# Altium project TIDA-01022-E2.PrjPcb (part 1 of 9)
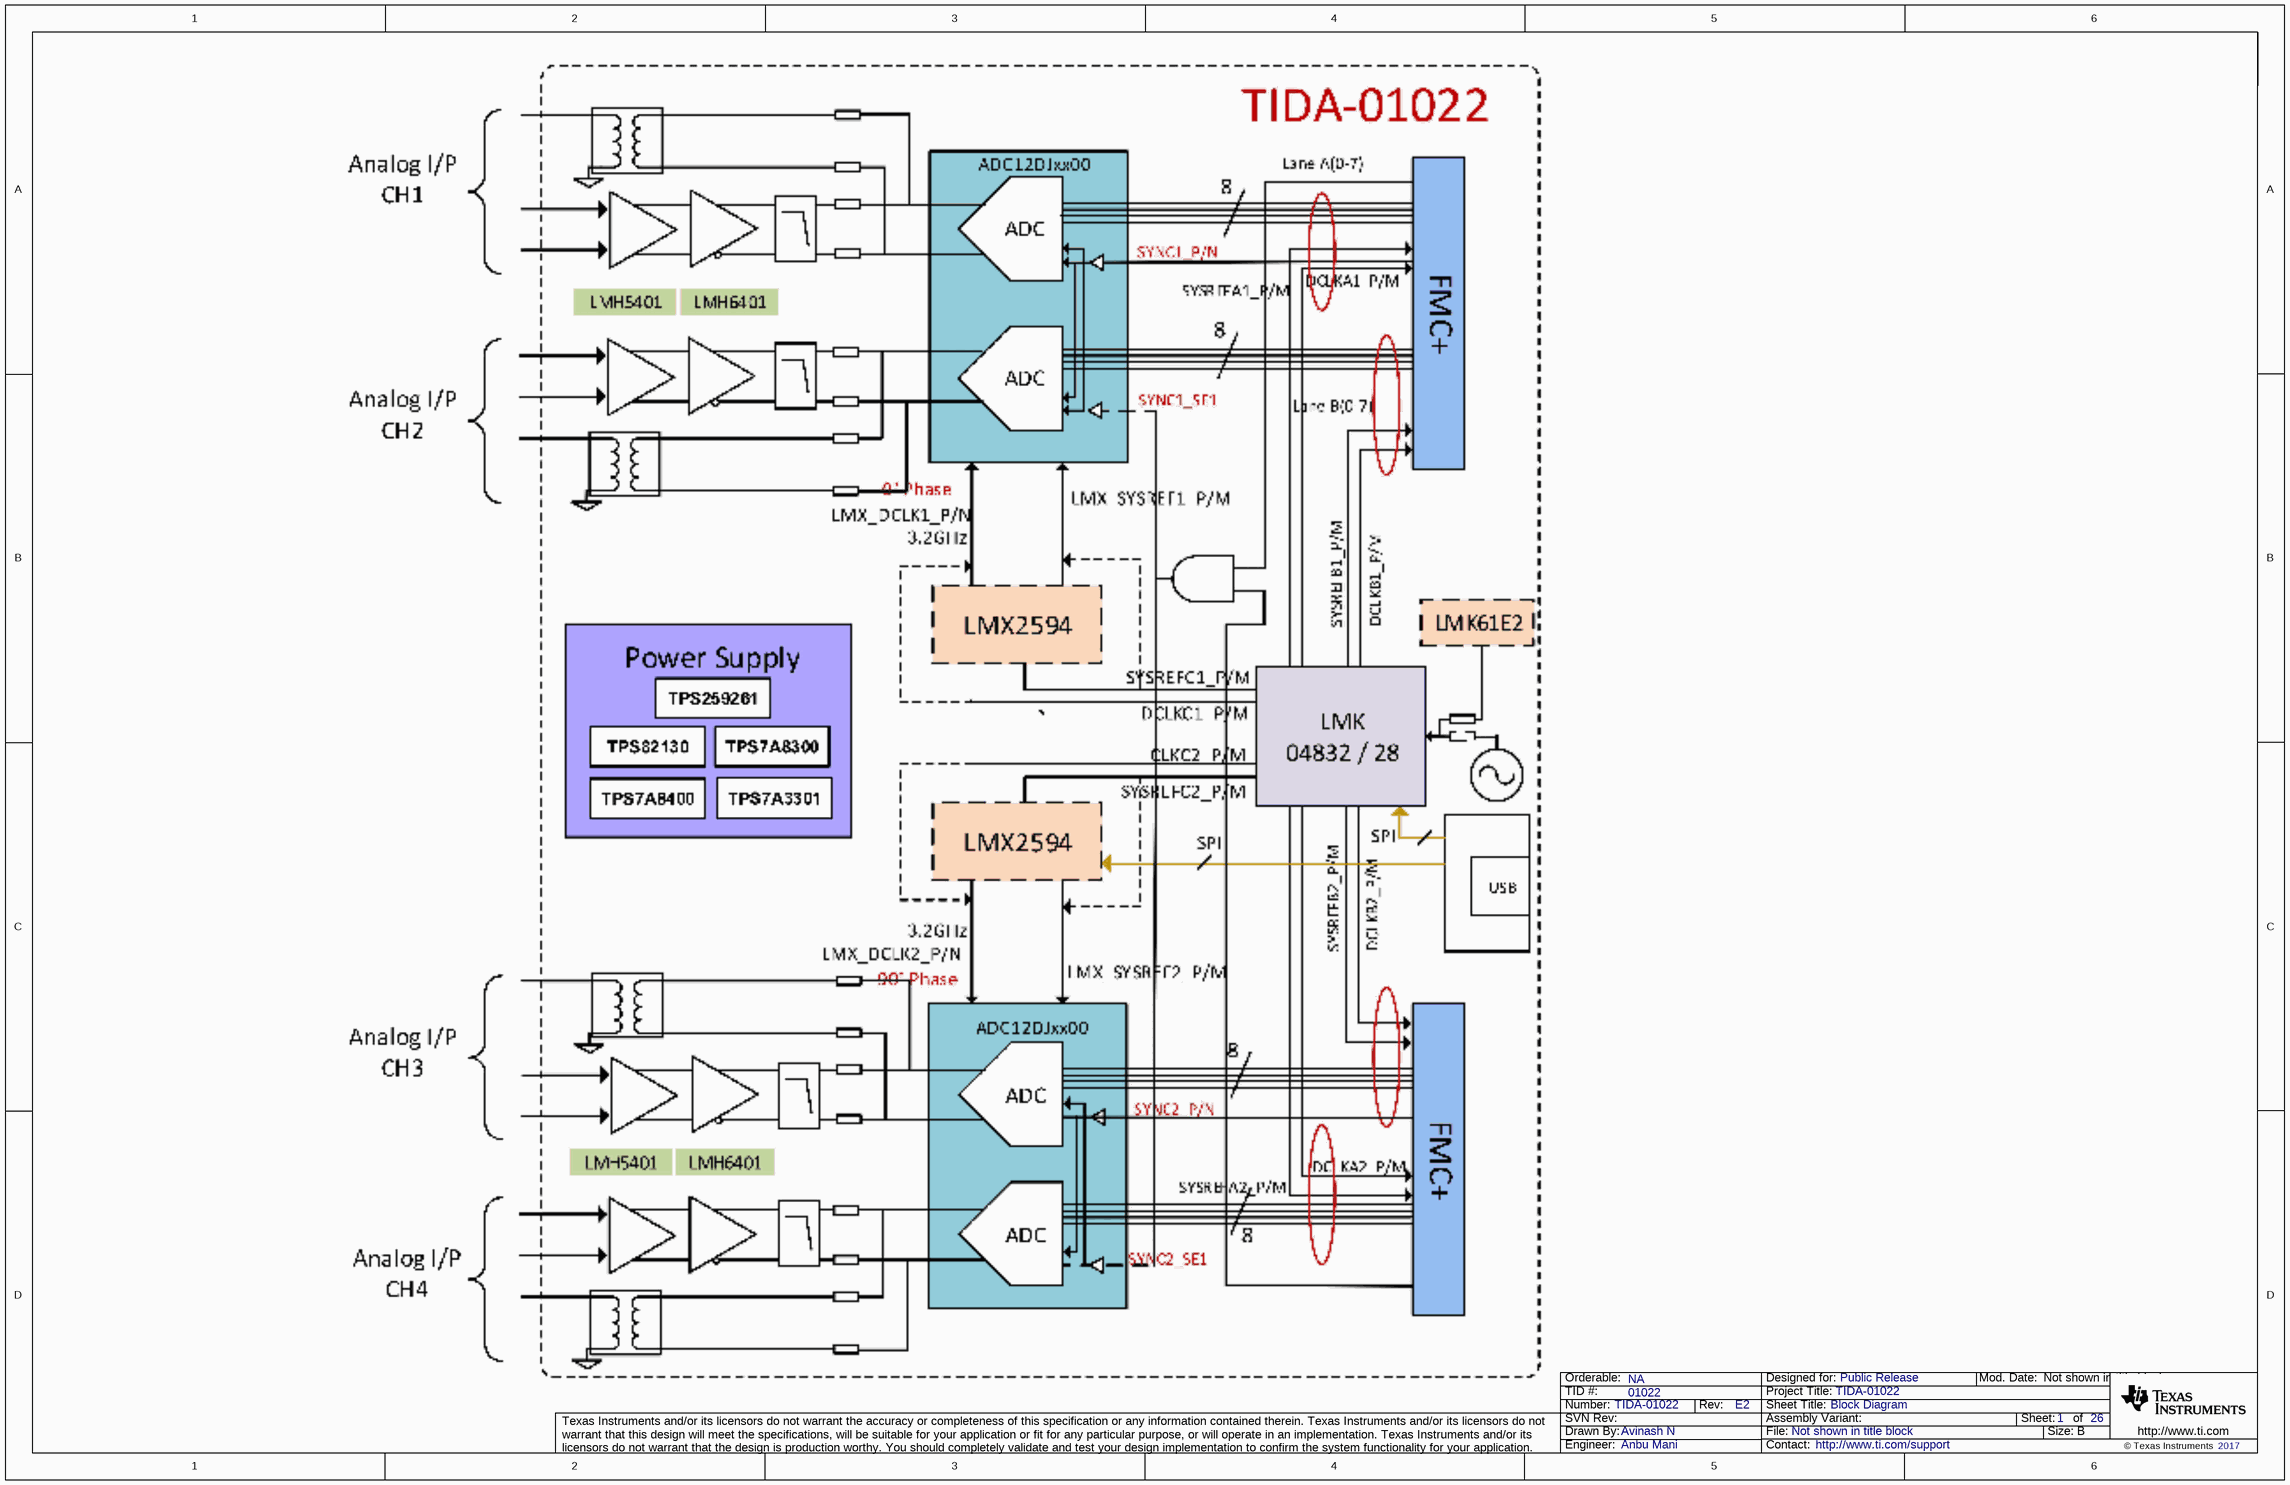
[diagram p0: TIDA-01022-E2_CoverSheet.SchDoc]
CopyrightYear: 2017; EVM_orderable: NA; PCB_Layout: Avinash N; PCB_Rev: E2; PRJ_Customer: Public Release; PRJ_Engineer: Anbu Mani; PRJ_Number: TIDA-01022; PRJ_Title: TIDA-01022; SCH_Rev: E2; TechSupport: http://www.ti.com/support; TID: 01022
26 sheets, 1781 parts. Net scope: flat (ports and power ports of the same name join across sheets).
Board file: TIDA-01022-E2.PcbDoc
Sheets:
  TIDA-01022-E2_CoverSheet.SchDoc
  TIDA-01022-E2_ADC ANALOG INP CH1.SchDoc
  TIDA-01022-E2_ADC ANALOG INP CH2.SchDoc
  TIDA-01022-E2_ADC ANALOG INP CH3.SchDoc
  TIDA-01022-E2_ADC ANALOG INP CH4.SchDoc
  TIDA-01022-E2_ADC12DJxx00_1.SchDoc
  TIDA-01022-E2_ADC12DJxx00_1PWR.SchDoc
  TIDA-01022-E2_ADC12DJxx00_2.SchDoc
  TIDA-01022-E2_ADC12DJxx00_2PWR.SchDoc
  TIDA-01022-E2_LMK00304_Buffer.SchDoc
  TIDA-01022-E2_LMK0482x.SchDoc
  TIDA-01022-E2_LMK0482x _PWR.SchDoc
  TIDA-01022-E2_LMX2594R_1.SchDoc
  TIDA-01022-E2_LMX2594R_2.SchDoc
  TIDA-01022-E2_Programming for ADC_LMK _LMX.SchDoc
  TIDA-01022-E2_USB.SchDoc
  TIDA-01022-E2_FMC+CONN1_1.SchDoc
  TIDA-01022-E2_FMC+CONN1_2.SchDoc
  TIDA-01022-E2_FMC+CONN2_1.SchDoc
  TIDA-01022-E2_FMC+CONN2_2.SchDoc
  TIDA-01022-E2_Power1.SchDoc
  TIDA-01022-E2_Power2.SchDoc
  TIDA-01022-E2_Power3.SchDoc
  TIDA-01022-E2_Power4.SchDoc
  TIDA-01022-E2_Power5.SchDoc
  TIDA-01022-E2_Hardware.SchDoc

## Sheet TIDA-01022-E2_CoverSheet.SchDoc: Block Diagram
size 431 x 279 mm; Date: Not shown in title block; ApprovedBy: Not shown in title block; CheckedBy: Not shown in title block; Author: Not shown in title block; CompanyName: Not shown in title block; DrawnBy: Avinash N; Engineer: Not shown in title block; Organization: Not shown in title block; Address1: Not shown in title block; Address2: Not shown in title block; Address3: Not shown in title block; Address4: Not shown in title block; DocumentNumber: 1; Revision: Use project parameter SCH_Rev; SheetNumber: 1; SheetTotal: 26; PageSetup: Record=PageOptions¦CenterHorizontal=True¦CenterVertical=True¦PrintScale=1.00¦XCorrection=1.00¦YCorrection=1.00¦PrintKind=0¦BorderSize=5000000¦LeftOffset=0¦BottomOffset=0¦Orientation=2¦PaperLength=1000¦PaperWidth=1000¦Scale=100¦PaperSource=15¦PrintQuality=600¦MediaType=1¦DitherType=10¦PaperKind=Letter¦PrintScaleMode=1

## Sheet TIDA-01022-E2_ADC ANALOG INP CH1.SchDoc: ADC ANALOG INP CH1
size 431 x 279 mm; Date: Not shown in title block; ApprovedBy: Not shown in title block; CheckedBy: Not shown in title block; Author: Not shown in title block; CompanyName: Not shown in title block; DrawnBy: Avinash N; Engineer: Not shown in title block; Organization: Not shown in title block; Address1: Not shown in title block; Address2: Not shown in title block; Address3: Not shown in title block; Address4: Not shown in title block; DocumentNumber: 1; Revision: Use project parameter SCH_Rev; SheetNumber: 2; SheetTotal: 26; PageSetup: Record=PageOptions¦CenterHorizontal=True¦CenterVertical=True¦PrintScale=1.00¦XCorrection=1.00¦YCorrection=1.00¦PrintKind=0¦BorderSize=5000000¦LeftOffset=0¦BottomOffset=0¦Orientation=2¦PaperLength=1000¦PaperWidth=1000¦Scale=100¦PaperSource=15¦PrintQuality=600¦MediaType=1¦DitherType=10¦PaperKind=Letter¦PrintScaleMode=1
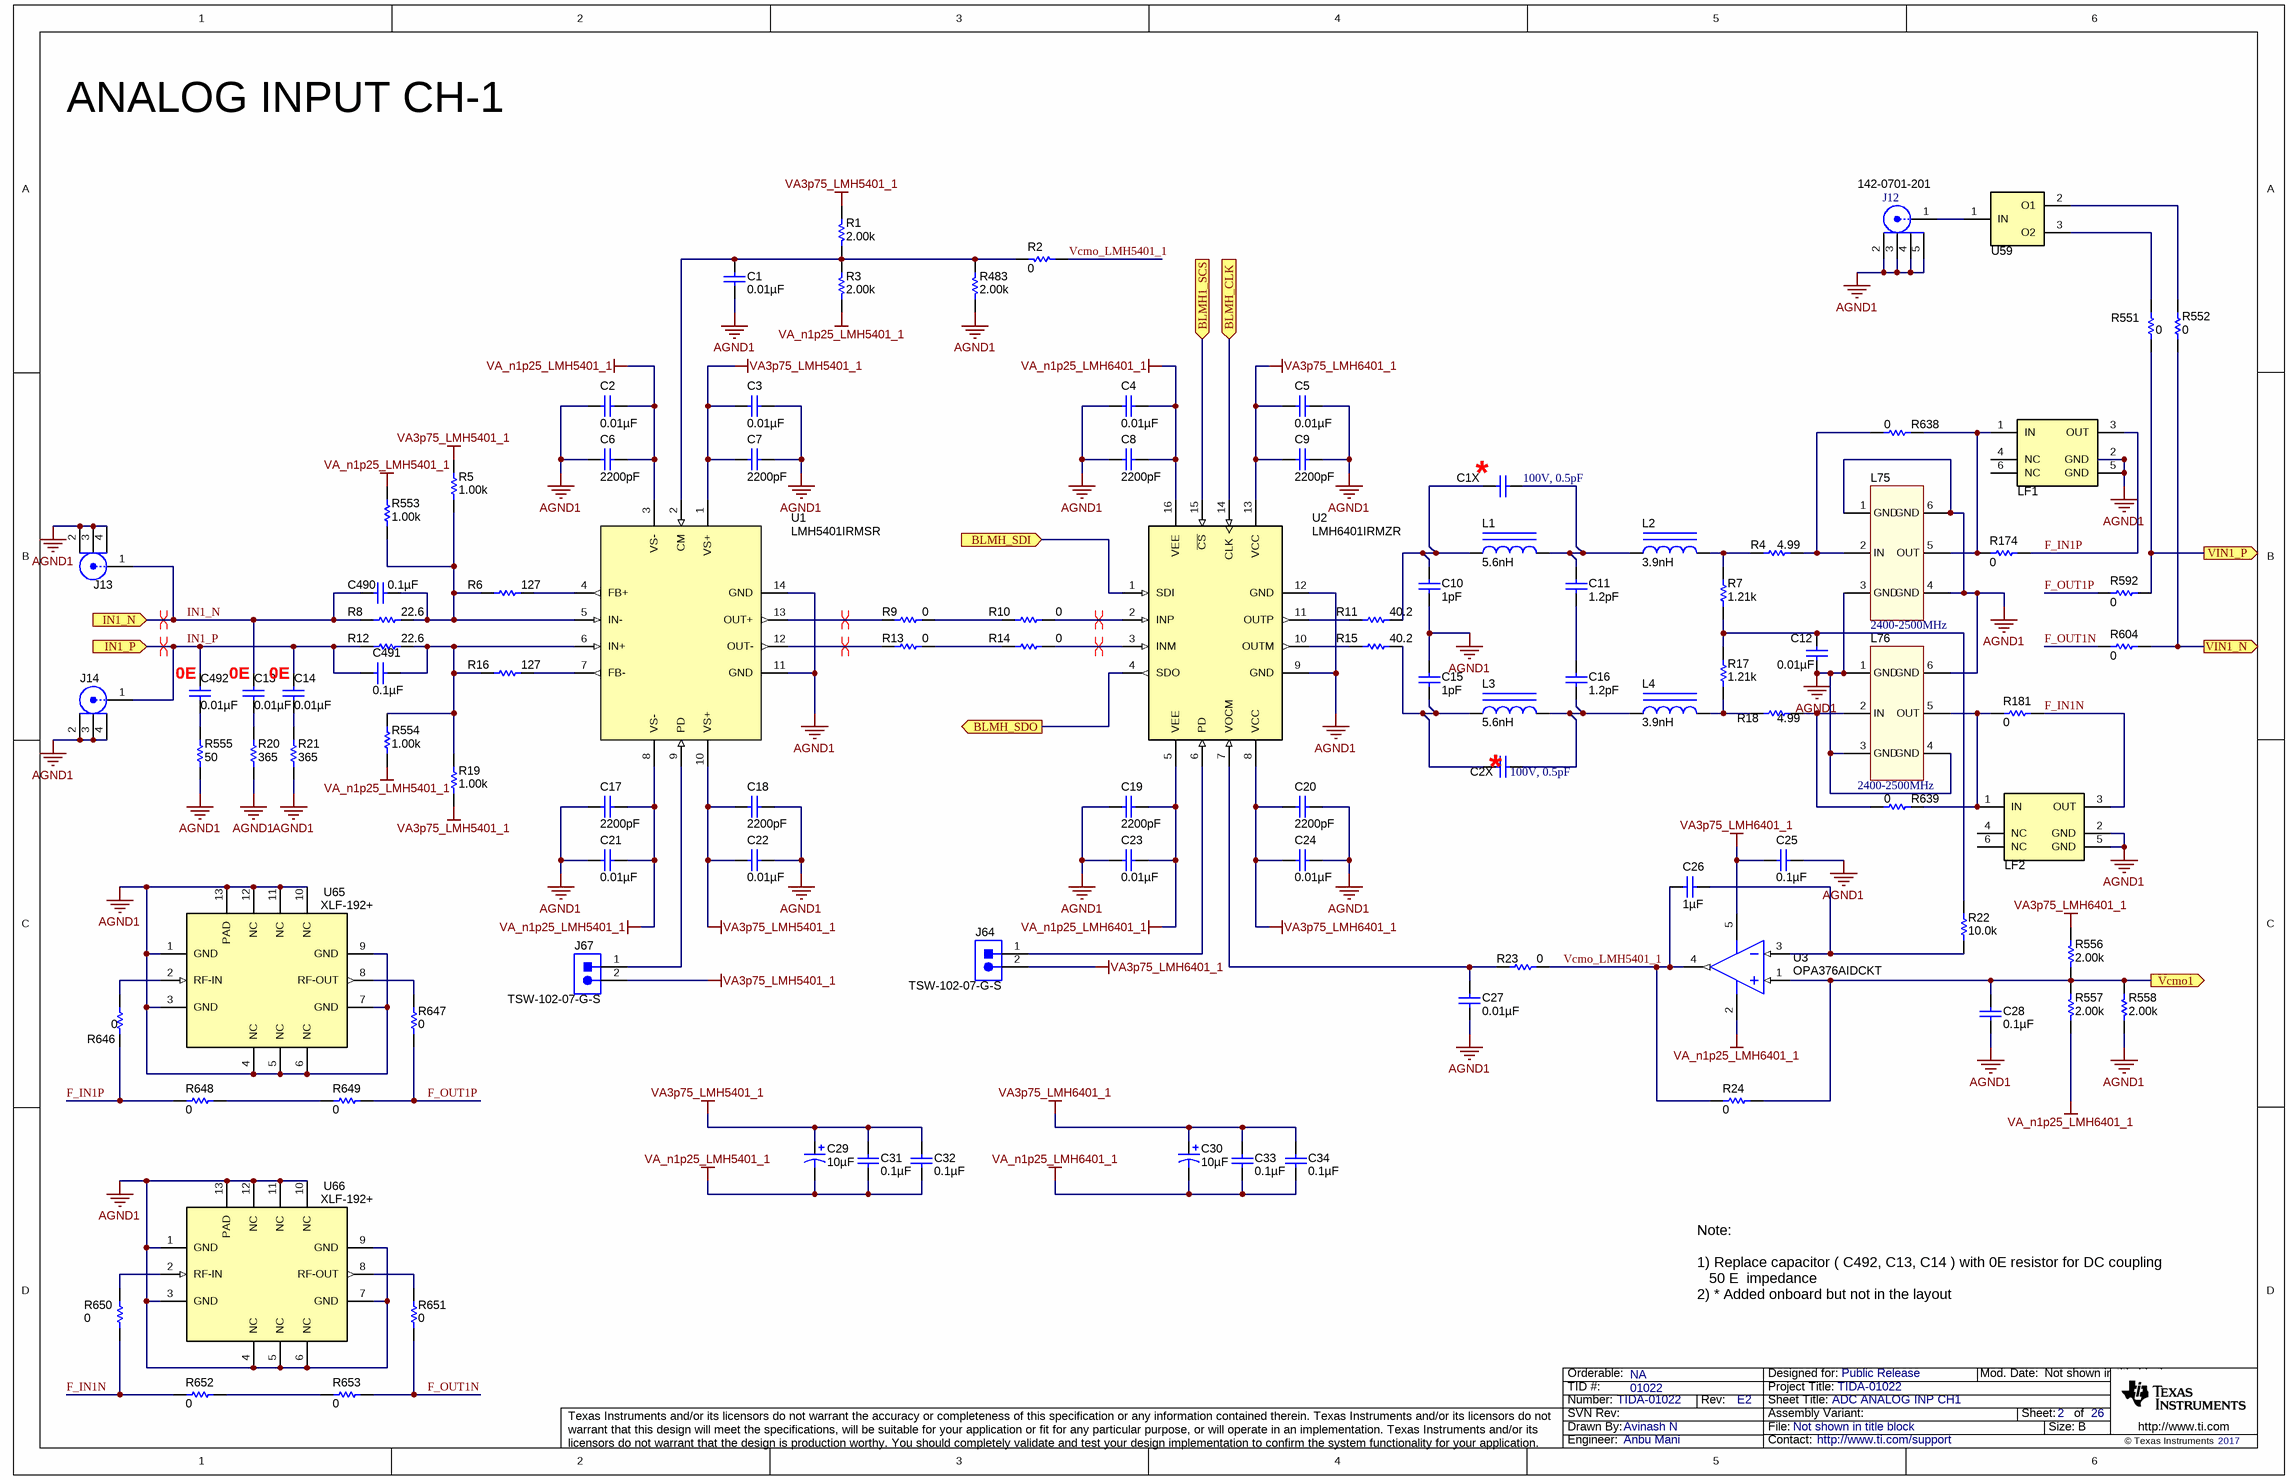
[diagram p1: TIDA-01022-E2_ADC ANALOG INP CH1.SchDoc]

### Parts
C1  ValueDisplayed: 0.01µF  [0402]  (hidden comment: GRM155R71E103KA01D)
C1X  100V, 0.5pF  [0603_1.6x0.8x0.8mm_Reflow Soldering]
C2  ValueDisplayed: 0.01µF  [0306]  (hidden comment: LLL185R71E103MA01L)
C2X  100V, 0.5pF  [0603_1.6x0.8x0.8mm_Reflow Soldering]
C3  ValueDisplayed: 0.01µF  [0306]  (hidden comment: LLL185R71E103MA01L)
C4  ValueDisplayed: 0.01µF  [0306]  (hidden comment: LLL185R71E103MA01L)
C5  ValueDisplayed: 0.01µF  [0306]  (hidden comment: LLL185R71E103MA01L)
C6  ValueDisplayed: 2200pF  [0306]  (hidden comment: LLL185R71H222MA01L)
C7  ValueDisplayed: 2200pF  [0306]  (hidden comment: LLL185R71H222MA01L)
C8  ValueDisplayed: 2200pF  [0306]  (hidden comment: LLL185R71H222MA01L)
C9  ValueDisplayed: 2200pF  [0306]  (hidden comment: LLL185R71H222MA01L)
C10  ValueDisplayed: 1pF  [0402]  (hidden comment: GRM1555C1H1R0CA01D)
C11  ValueDisplayed: 1.2pF  [0402]  (hidden comment: GRM1555C1H1R2BA01D)
C12  ValueDisplayed: 0.01µF  [0402]  (hidden comment: GRM155R71E103KA01D)
C13  ValueDisplayed: 0.01µF  [0402]  (hidden comment: GRM155R71E103KA01D)
C14  ValueDisplayed: 0.01µF  [0402]  (hidden comment: GRM155R71E103KA01D)
C15  ValueDisplayed: 1pF  [0402]  (hidden comment: GRM1555C1H1R0CA01D)
C16  ValueDisplayed: 1.2pF  [0402]  (hidden comment: GRM1555C1H1R2BA01D)
C17  ValueDisplayed: 2200pF  [0306]  (hidden comment: LLL185R71H222MA01L)
C18  ValueDisplayed: 2200pF  [0306]  (hidden comment: LLL185R71H222MA01L)
C19  ValueDisplayed: 2200pF  [0306]  (hidden comment: LLL185R71H222MA01L)
C20  ValueDisplayed: 2200pF  [0306]  (hidden comment: LLL185R71H222MA01L)
C21  ValueDisplayed: 0.01µF  [0306]  (hidden comment: LLL185R71E103MA01L)
C22  ValueDisplayed: 0.01µF  [0306]  (hidden comment: LLL185R71E103MA01L)
C23  ValueDisplayed: 0.01µF  [0306]  (hidden comment: LLL185R71E103MA01L)
C24  ValueDisplayed: 0.01µF  [0306]  (hidden comment: LLL185R71E103MA01L)
C25  ValueDisplayed: 0.1µF  [0402]  (hidden comment: C1005X5R1A104K050BA)
C26  ValueDisplayed: 1µF  [0603]  (hidden comment: C1608X5R1A105K080AC)
C27  ValueDisplayed: 0.01µF  [0402]  (hidden comment: GRM155R71E103KA01D)
C28  ValueDisplayed: 0.1µF  [0402]  (hidden comment: C1005X5R1A104K050BA)
C29  ValueDisplayed: 10µF  [3216-18]  (hidden comment: TPSA106K010R0900)
C30  ValueDisplayed: 10µF  [3216-18]  (hidden comment: TPSA106K010R0900)
C31  ValueDisplayed: 0.1µF  [0402]  (hidden comment: C1005X5R1A104K050BA)
C32  ValueDisplayed: 0.1µF  [0402]  (hidden comment: C1005X5R1A104K050BA)
C33  ValueDisplayed: 0.1µF  [0402]  (hidden comment: C1005X5R1A104K050BA)
C34  ValueDisplayed: 0.1µF  [0402]  (hidden comment: C1005X5R1A104K050BA)
C490  ValueDisplayed: 0.1µF  [0402]  (hidden comment: GRM155R71C104JA88D)
C491  ValueDisplayed: 0.1µF  [0402]  (hidden comment: GRM155R71C104JA88D)
C492  ValueDisplayed: 0.01µF  [0402]  (hidden comment: GRM155R71E103KA01D)
J12  142-0701-201  [Johnson_142-0701-20x]
J13  142-0771-831  [Johnson_142-0771-831]  (value not drawn)
J14  142-0771-831  [Johnson_142-0771-831]  (value not drawn)
J64  TSW-102-07-G-S  [TSW-102-07-G-S]
J67  TSW-102-07-G-S  [TSW-102-07-G-S]
L1  ValueDisplayed: 5.6nH  [LQW18A]  (hidden comment: LQW18AN5N6D10D)
L2  ValueDisplayed: 3.9nH  [0603HC]  (hidden comment: 0603HC-3N9XJLU)
L3  ValueDisplayed: 5.6nH  [LQW18A]  (hidden comment: LQW18AN5N6D10D)
L4  ValueDisplayed: 3.9nH  [0603HC]  (hidden comment: 0603HC-3N9XJLU)
L75  value 2400-2500MHz  [WE-LPF_0603]  (hidden comment: WE-LPF, 748112024)
L76  value 2400-2500MHz  [WE-LPF_0603]  (hidden comment: WE-LPF, 748112024)
LF1  LFL182G45TC3B746  [FIL_LFL18_TC1]  (value not drawn)
LF2  LFL182G45TC3B746  [FIL_LFL18_TC1]  (value not drawn)
R1  ValueDisplayed: 2.00k  [0402]  (hidden comment: CRCW04022K00FKED)
R2  ValueDisplayed: 0  [0402]  (hidden comment: CRCW04020000Z0ED)
R3  ValueDisplayed: 2.00k  [0402]  (hidden comment: CRCW04022K00FKED)
R4  ValueDisplayed: 4.99  [0402]  (hidden comment: CRCW04024R99FKED)
R5  ValueDisplayed: 1.00k  [0402]  (hidden comment: ERJ-2RKF1001X)
R6  ValueDisplayed: 127  [0402]  (hidden comment: CRCW0402127RFKED)
R7  ValueDisplayed: 1.21k  [0402]  (hidden comment: CRCW04021K21FKED)
R8  ValueDisplayed: 22.6  [0402]  (hidden comment: CRCW040222R6FKED)
R9  ValueDisplayed: 0  [0402]  (hidden comment: CRCW04020000Z0ED)
R10  ValueDisplayed: 0  [0402]  (hidden comment: CRCW04020000Z0ED)
R11  ValueDisplayed: 40.2  [0402]  (hidden comment: CRCW040240R2FKED)
R12  ValueDisplayed: 22.6  [0402]  (hidden comment: CRCW040222R6FKED)
R13  ValueDisplayed: 0  [0402]  (hidden comment: CRCW04020000Z0ED)
R14  ValueDisplayed: 0  [0402]  (hidden comment: CRCW04020000Z0ED)
R15  ValueDisplayed: 40.2  [0402]  (hidden comment: CRCW040240R2FKED)
R16  ValueDisplayed: 127  [0402]  (hidden comment: CRCW0402127RFKED)
R17  ValueDisplayed: 1.21k  [0402]  (hidden comment: CRCW04021K21FKED)
R18  ValueDisplayed: 4.99  [0402]  (hidden comment: CRCW04024R99FKED)
R19  ValueDisplayed: 1.00k  [0402]  (hidden comment: ERJ-2RKF1001X)
R20  ValueDisplayed: 365  [0402]  (hidden comment: CRCW0402365RFKED)
R21  ValueDisplayed: 365  [0402]  (hidden comment: CRCW0402365RFKED)
R22  ValueDisplayed: 10.0k  [0402]  (hidden comment: CRCW040210K0FKED)
R23  ValueDisplayed: 0  [0402]  (hidden comment: CRCW04020000Z0ED)
R24  ValueDisplayed: 0  [0402]  (hidden comment: CRCW04020000Z0ED)
R174  ValueDisplayed: 0  [0402_FILTER]  (hidden comment: CRCW04020000Z0ED)
R181  ValueDisplayed: 0  [0402_FILTER]  (hidden comment: CRCW04020000Z0ED)
R483  ValueDisplayed: 2.00k  [0402]  (hidden comment: CRCW04022K00FKED)
R551  ValueDisplayed: 0  [0201_adc]  (hidden comment: CRCW02010000Z0ED)
R552  ValueDisplayed: 0  [0201_adc]  (hidden comment: CRCW02010000Z0ED)
R553  ValueDisplayed: 1.00k  [0402]  (hidden comment: ERJ-2RKF1001X)
R554  ValueDisplayed: 1.00k  [0402]  (hidden comment: ERJ-2RKF1001X)
R555  ValueDisplayed: 50  [0402]  (hidden comment: FC0402E50R0BTBST1)
R556  ValueDisplayed: 2.00k  [0402]  (hidden comment: CRCW04022K00FKED)
R557  ValueDisplayed: 2.00k  [0402]  (hidden comment: CRCW04022K00FKED)
R558  ValueDisplayed: 2.00k  [0402]  (hidden comment: CRCW04022K00FKED)
R592  ValueDisplayed: 0  [0201_adc]  (hidden comment: CRCW02010000Z0ED)
R604  ValueDisplayed: 0  [0201_adc]  (hidden comment: CRCW02010000Z0ED)
R638  ValueDisplayed: 0  [0402_FILTER]  (hidden comment: CRCW04020000Z0ED)
R639  ValueDisplayed: 0  [0402_FILTER]  (hidden comment: CRCW04020000Z0ED)
R646  ValueDisplayed: 0  [0201_adc]  (hidden comment: CRCW02010000Z0ED)
R647  ValueDisplayed: 0  [0201_adc]  (hidden comment: CRCW02010000Z0ED)
R648  ValueDisplayed: 0  [0201_adc]  (hidden comment: CRCW02010000Z0ED)
R649  ValueDisplayed: 0  [0201_adc]  (hidden comment: CRCW02010000Z0ED)
R650  ValueDisplayed: 0  [0201_adc]  (hidden comment: CRCW02010000Z0ED)
R651  ValueDisplayed: 0  [0201_adc]  (hidden comment: CRCW02010000Z0ED)
R652  ValueDisplayed: 0  [0201_adc]  (hidden comment: CRCW02010000Z0ED)
R653  ValueDisplayed: 0  [0201_adc]  (hidden comment: CRCW02010000Z0ED)
U1  LMH5401IRMSR  [RMS0014A]
U2  LMH6401IRMZR  [RMZ0016A]
U3  OPA376AIDCKT  [DCK0005A_N]
U59  BAL-0006SMG  [Marki_BAL-0006SMG]  (value not drawn)
U65  XLF-192+  [DQ1225]
U66  XLF-192+  [DQ1225]

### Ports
BLMH1_SCS (in), BLMH_CLK (in), BLMH_SDI (in), BLMH_SDO (out), IN1_N (in), IN1_P (in), Vcmo1 (out), VIN1_N (out), VIN1_P (out)

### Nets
AGND1: C1.2 C2.1 C3.1 C4.1 C5.1 C6.2 C7.2 C8.2 C9.2 C10.2 C12.2 C15.2 C17.2 C18.2 C19.2 C20.2 C21.1 C22.1 C23.1 C24.1 C25.1 C27.2 C28.2 J12.2 J12.3 J12.4 J12.5 J13.2 J13.3 J13.4 J14.2 J14.3 J14.4 L75.1(GND) L75.3(GND) L75.4(GND) L75.6(GND) L76.1(GND) L76.3(GND) L76.4(GND) L76.6(GND) LF1.2(GND) LF1.5(GND) LF2.2(GND) LF2.5(GND) R20.1 R21.1 R483.1 R555.1 R558.1 U1.11(GND) U1.14(GND) U2.9(GND) U2.12(GND) U65.1(GND) U65.3(GND) U65.4(NC) U65.5(NC) U65.6(NC) U65.7(GND) U65.9(GND) U65.10(NC) U65.11(NC) U65.12(NC) U65.13(PAD) U66.1(GND) U66.3(GND) U66.4(NC) U66.5(NC) U66.6(NC) U66.7(GND) U66.9(GND) U66.10(NC) U66.11(NC) U66.12(NC) U66.13(PAD)  [project net AGND]
VA3p75_LMH5401_1: C3.2 C7.1 C18.1 C22.2 C29.1(+) C31.1 C32.1 J67.2 R1.2 R5.2 R19.1 U1.1(VS+) U1.10(VS+)
VA3p75_LMH6401_1: C5.2 C9.1 C20.1 C24.2 C25.2 C30.1(+) C33.1 C34.1 J64.2 R556.2 U2.8(VCC) U2.13(VCC) U3.5(V+)
VA_n1p25_LMH5401_1: C2.2 C6.1 C17.1 C21.2 C29.2(-) C31.2 C32.2 R3.1 R553.2 R554.2 U1.3(VS-) U1.8(VS-)
VA_n1p25_LMH6401_1: C4.2 C8.1 C19.1 C23.2 C30.2(-) C33.2 C34.2 R557.1 U2.5(VEE) U2.16(VEE) U3.2(V-)
BLMH1_SCS: U2.15(~{CS}) ; port BLMH1_SCS
BLMH_CLK: U2.14(CLK) ; port BLMH_CLK
BLMH_SDI: U2.1(SDI) ; port BLMH_SDI
BLMH_SDO: U2.4(SDO) ; port BLMH_SDO
F_IN1N: LF2.3(OUT) R181.2 R650.1 R652.1
F_IN1P: LF1.3(OUT) R174.2 R646.1 R648.1
F_OUT1N: R604.1 R651.1 R653.2
F_OUT1P: R592.1 R647.1 R649.2
IN1_N: C13.1 C490.2 J13.1 R8.1 ; port IN1_N
IN1_P: C14.1 C491.1 C492.1 J14.1 R12.1 ; port IN1_P
Vcmo1: C28.1 R24.1 R556.1 R557.2 R558.2 U3.1(IN+) ; port Vcmo1
Vcmo_LMH5401_1: C26.1 R2.2 R23.1 R24.2 U3.4(OUT)
VIN1_N: R552.2 R604.2 ; port VIN1_N
VIN1_P: R551.2 R592.2 ; port VIN1_P
NetC1_1: C1.1 R1.1 R2.1 R3.2 R483.2 U1.2(CM)
NetC1X_1: C1X.1 C10.1 L1.1 R11.1
NetC1X_2: C1X.2 C11.1 L1.2 L2.1
NetC2X_1: C2X.1 C15.1 L3.1 R15.1
NetC2X_2: C2X.2 C16.1 L3.2 L4.1
NetC11_2: C11.2 C16.2
NetC12_1: C12.1 R7.1 R17.1 R22.2
NetC13_2: C13.2 R20.2
NetC14_2: C14.2 R21.2
NetC26_2: C26.2 R22.1 U3.3(IN-)
NetC27_1: C27.1 R23.2 U2.7(VOCM)
NetC490_1: C490.1 R5.1 R6.1 R8.2 R553.1 U1.5(IN-)
NetC491_2: C491.2 R12.2 R16.1 R19.2 R554.1 U1.6(IN+)
NetC492_2: C492.2 R555.2
NetJ12_1: J12.1 U59.1(IN)
NetJ64_1: J64.1 U2.6(PD)
NetJ67_1: J67.1 U1.9(PD)
NetL2_2: L2.2 R4.1 R7.2
NetL4_2: L4.2 R17.2 R18.1
NetL75_2: L75.2(IN) R4.2 R638.1
NetL75_5: L75.5(OUT) LF1.1(IN) R174.1 R638.2
NetL76_2: L76.2(IN) R18.2 R639.1
NetL76_5: L76.5(OUT) LF2.1(IN) R181.1 R639.2
NetR6_2: R6.2 U1.4(FB+)
NetR9_1: R9.1 U1.13(OUT+)
NetR9_2: R9.2 R10.2
NetR10_1: R10.1 U2.2(INP)
NetR11_2: R11.2 U2.11(OUTP)
NetR13_1: R13.1 U1.12(OUT-)
NetR13_2: R13.2 R14.2
NetR14_1: R14.1 U2.3(INM)
NetR15_2: R15.2 U2.10(OUTM)
NetR16_2: R16.2 U1.7(FB-)
NetR551_1: R551.1 U59.3(O2)
NetR552_1: R552.1 U59.2(O1)
NetR646_2: R646.2 U65.2(RF-IN)
NetR647_2: R647.2 U65.8(RF-OUT)
NetR648_2: R648.2 R649.1
NetR650_2: R650.2 U66.2(RF-IN)
NetR651_2: R651.2 U66.8(RF-OUT)
NetR652_2: R652.2 R653.1

Not connected (* = marked no-connect by the designer): LF1 4(NC) 6(NC); LF2 4(NC) 6(NC)

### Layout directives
differential pair: IN1_N, IN1_P, NetR9_1, NetR10_1, NetR13_1, NetR14_1

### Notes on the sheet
- ANALOG INPUT CH-1
- (near C1X) *
- (near C492) 0E
- (near C13) 0E
- (near C14) 0E
- (near C2X) *
- Note:
  1) Replace capacitor ( C492, C13, C14 ) with 0E resistor for DC coupling
  50 E  impedance
  2) * Added onboard but not in the layout

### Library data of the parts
C1 C12-C14 C27 C492 = GRM155R71E103KA01D: CAP, CERM, 0.01 µF, 25 V, +/- 10%, X7R, 0402; Manufacturer: MuRata; Polarized: N; CompType: Capacitor; Value: 0.01uF; U/M: EA; Cap_F: 0.00000001; Tolerance_%: 10; Value1: Unknown; VDC_V: 25; Value2: 25V; TaMin_C: -55; TaMax_C: 125; SizeArea_mm2: 0.5; SizeAreaWB_mm2: 3; SizeX_mm: 1; SizeZ_mm: 0.6; AEC Category: Q200
C1X C2X = 885012006086: WCAP-CSGP Ceramic Capacitors, 0603, NP0, 100V, 0.5pF; Rated Voltage: 100V DC
C2-C5 C21-C24 = LLL185R71E103MA01L: CAP, CERM, 0.01 µF, 25 V, +/- 20%, X7R, 0306; Manufacturer: MuRata; Polarized: N; CompType: Capacitor; Value: 0.01uF; U/M: EA; Cap_F: 0.00000001; Tolerance_%: 20; Value1: Unknown; VDC_V: 25; Value2: 25V; TaMin_C: -55; TaMax_C: 125; SizeArea_mm2: 1.28; SizeAreaWB_mm2: 4.68; SizeX_mm: 0.8; SizeY_mm: 1.6; SizeZ_mm: 0.6; AEC Category: Q200
C6-C9 C17-C20 = LLL185R71H222MA01L: CAP, CERM, 2200 pF, 50 V, +/- 20%, X7R, 0306; Manufacturer: MuRata; Polarized: N; CompType: Capacitor; Value: 2200pF; U/M: EA; Cap_F: 0.0000000022; Tolerance_%: 20; Value1: Unknown; VDC_V: 50; Value2: 50V; TaMin_C: -55; TaMax_C: 125; SizeArea_mm2: 1.28; SizeAreaWB_mm2: 4.68; SizeX_mm: 0.8; SizeY_mm: 1.6; SizeZ_mm: 0.6; AEC Category: Q200
C10 C15 = GRM1555C1H1R0CA01D: CAP, CERM, 1 pF, 50 V, +/- 5%, C0G/NP0, 0402; Manufacturer: MuRata; Polarized: N; CompType: Capacitor; Value: 1pF; U/M: EA; Cap_F: 0.000000000001; Tolerance_%: 5; Value1: Unknown; VDC_V: 50; Value2: 50V; TaMin_C: -55; TaMax_C: 125; SizeArea_mm2: 0.5; SizeAreaWB_mm2: 3; SizeX_mm: 1; SizeZ_mm: 0.6; AEC Category: Q200
C11 C16 = GRM1555C1H1R2BA01D: CAP, CERM, 1.2 pF, 50 V, +/- 8.3%, C0G/NP0, 0402; Manufacturer: MuRata; Polarized: N; CompType: Capacitor; Value: 1.2pF; U/M: EA; Cap_F: 0.0000000000012; Tolerance_%: 8.3; Value1: Unknown; VDC_V: 50; Value2: 50V; TaMin_C: -55; TaMax_C: 125; SizeArea_mm2: 0.5; SizeAreaWB_mm2: 3; SizeX_mm: 1; SizeZ_mm: 0.6; AEC Category: Q200
C25 C28 C31-C34 = C1005X5R1A104K050BA: CAP, CERM, 0.1 µF, 10 V, +/- 10%, X5R, 0402; Manufacturer: TDK; Polarized: N; CompType: Capacitor; Value: 0.1uF; U/M: EA; Cap_F: 0.0000001; Tolerance_%: 10; Value1: Unknown; Value2: 10V; TaMin_C: -55; TaMax_C: 85; SizeArea_mm2: 0.5; SizeAreaWB_mm2: 3; SizeX_mm: 1; SizeZ_mm: 0.6; AEC Category: Q200
C26 = C1608X5R1A105K080AC: CAP, CERM, 1 µF, 10 V, +/- 10%, X5R, 0603; Manufacturer: TDK; Polarized: N; CompType: Capacitor; Value: 1uF; U/M: EA; Cap_F: 0.000001; Tolerance_%: 10; Value1: Unknown; Value2: 10V; TaMin_C: -55; TaMax_C: 85; SizeArea_mm2: 1.28; SizeAreaWB_mm2: 4.68; SizeX_mm: 1.6; SizeY_mm: 0.8; SizeZ_mm: 1; AEC Category: Q200
C29 C30 = TPSA106K010R0900: CAP, TA, 10 µF, 10 V, +/- 10%, 0.9 ohm, SMD; Manufacturer: AVX; Polarized: Y; CompType: Capacitor; Value: 10uF; U/M: EA; Cap_F: 0.00001; Tolerance_%: 10; Value1: 0.9 ohm; Value2: 10V; ESR_ohm: 0.9; IRMS_A: 0.26; TaMin_C: -55; TaMax_C: 125; Cap_Case: A; SizeAreaWB_mm2: 10.92; SizeArea_mm2: 5.12; SizeX_mm: 3.2; SizeY_mm: 1.6; SizeZ_mm: 1.8; AEC Category: Q200
C490 C491 = GRM155R71C104JA88D: CAP, CERM, 0.1 µF, 16 V, +/- 5%, X7R, 0402; Manufacturer: MuRata; Polarized: N; CompType: Capacitor; Value: 0.1uF; U/M: EA; Cap_F: 0.0000001; Tolerance_%: 5; Value1: Unknown; VDC_V: 16; Value2: 16V; TaMin_C: -55; TaMax_C: 125; SizeArea_mm2: 0.5; SizeAreaWB_mm2: 3; SizeX_mm: 1; SizeZ_mm: 0.6; AEC Category: Q200
J12 = 142-0701-201: Connector, TH, SMA; Manufacturer: Emerson Network Power; SymbolCreator: X0208326
J13 J14 = 142-0771-831: JACK, SMA, 50 Ohm, Gold, Edge Mount; Manufacturer: Johnson; SymbolCreator: Altium; Gender: Female; Voltage_V: 170
J64 J67 = TSW-102-07-G-S: Header, 100mil, 2x1, Gold, TH; Manufacturer: Samtec; SymbolCreator: a0412235; Pitch_mm: 2.54; Gender: Male; Shrouded: N; Row_Count: 1; Current_A: 6.3; Voltage_V: 550; Cert_CSA: Y
L1 L3 = LQW18AN5N6D10D: Inductor, Wirewound, 5.6 nH, 0.9 A, 0.045 ohm, SMD; Manufacturer: MuRata; Value: 5.6nH; Ind_H: 5.6E-9; Imax_A: 0.9; Irms: 0.9A @ C rise; DCR_ohm: 0.045; Value2: 0.9A; SizeAreaWB_mm2: 4.68; SizeArea_mm2: 1.28; SizeX_mm: 1.6; SizeY_mm: 0.8; SizeZ_mm: 1; AEC Category: Q200; AEC Qualified: N
L2 L4 = 0603HC-3N9XJLU: Inductor, Wirewound, Ceramic, 3.9 nH, 2.2 A, 0.054 ohm, SMD; Manufacturer: Coilcraft; Value: 3.9nH; Ind_H: 3.9E-9; Imax_A: 2.2; Irms: 2.4A @ 20C rise; DCR_ohm: 0.054; Value2: 2.2A; SizeAreaWB_mm2: 5.936; SizeArea_mm2: 2.016; SizeX_mm: 1.8; SizeY_mm: 1.12; SizeZ_mm: 1.02; AEC Category: Q200
L75 L76 = WE-LPF, 748112024: WE-LPF Multilayer Chip Low-Pass Filter, size 0603, 2400-2500MHz
LF1 LF2 = LFL182G45TC3B746: Filter for Communication Equipment, SMD; Manufacturer: MuRata; SymbolCreator: Altium; SizeAreaWB_mm2: 4.68; SizeArea_mm2: 1.28; SizeX_mm: 1.6; SizeY_mm: 0.8; SizeZ_mm: 0.7
R1 R3 R483 R556-R558 = CRCW04022K00FKED: RES, 2.00 k, 1%, 0.063 W, 0402; Manufacturer: Vishay-Dale; CompType: Resistor; Value: 2.00k; Res_ohm: 2000; Value_Code: 2k00; Tolerance_%: 1; Power_W: 0.063; Value2: 0.063W; VDC_V: 50; TempCo: 100 ppm/C; SizeArea_mm2: 0.5; SizeZ_mm: 0.6; EIA_Code: E96; U/M: EA; AEC Category: Q200
R2 R9 R10 R13 R14 R23 R24 R174 R181 R638 R639 = CRCW04020000Z0ED: RES, 0, 5%, 0.063 W, 0402; Manufacturer: Vishay-Dale; CompType: Resistor; Value: 0; Value_Code: 0000; Tolerance_%: 5; Power_W: 0.063; Value2: 0.063W; VDC_V: 50; TempCo: 200 ppm/C; SizeArea_mm2: 0.5; SizeX_mm: 1; SizeZ_mm: 0.6; EIA_Code: E24; U/M: EA; AEC Category: Q200
R4 R18 = CRCW04024R99FKED: RES, 4.99, 1%, 0.063 W, 0402; Manufacturer: Vishay-Dale; CompType: Resistor; Value: 4.99; Value_Code: 4R99; Tolerance_%: 1; Power_W: 0.063; Value2: 0.063W; VDC_V: 50; TempCo: 100 ppm/C; SizeArea_mm2: 0.5; SizeZ_mm: 0.6; EIA_Code: E96; U/M: EA; AEC Category: Q200
R5 R19 R553 R554 = ERJ-2RKF1001X: RES, 1.00 k, 1%, 0.1 W, 0402; Manufacturer: Panasonic; CompType: Resistor; Value: 1.00k; Res_ohm: 1000; Value_Code: 1k00; Tolerance_%: 1; Power_W: 0.1; Value2: 0.1W; VDC_V: 50; TempCo: 100 ppm/C; SizeArea_mm2: 0.5; SizeZ_mm: 0.6; EIA_Code: E96; U/M: EA; AEC Category: Q200
R6 R16 = CRCW0402127RFKED: RES, 127, 1%, 0.063 W, 0402; Manufacturer: Vishay-Dale; CompType: Resistor; Value: 127; Value_Code: 127R; Tolerance_%: 1; Power_W: 0.063; Value2: 0.063W; VDC_V: 50; TempCo: 100 ppm/C; SizeArea_mm2: 0.5; SizeZ_mm: 0.6; EIA_Code: E96; U/M: EA; AEC Category: Q200
R7 R17 = CRCW04021K21FKED: RES, 1.21 k, 1%, 0.063 W, 0402; Manufacturer: Vishay-Dale; CompType: Resistor; Value: 1.21k; Res_ohm: 1210; Value_Code: 1k21; Tolerance_%: 1; Power_W: 0.063; Value2: 0.063W; VDC_V: 50; TempCo: 100 ppm/C; SizeArea_mm2: 0.5; SizeZ_mm: 0.6; EIA_Code: E96; U/M: EA; AEC Category: Q200
R8 R12 = CRCW040222R6FKED: RES, 22.6, 1%, 0.063 W, 0402; Manufacturer: Vishay-Dale; CompType: Resistor; Value: 22.6; Value_Code: 22R6; Tolerance_%: 1; Power_W: 0.063; Value2: 0.063W; VDC_V: 50; TempCo: 100 ppm/C; SizeArea_mm2: 0.5; SizeZ_mm: 0.6; EIA_Code: E96; U/M: EA; AEC Category: Q200
R11 R15 = CRCW040240R2FKED: RES, 40.2, 1%, 0.063 W, 0402; Manufacturer: Vishay-Dale; CompType: Resistor; Value: 40.2; Value_Code: 40R2; Tolerance_%: 1; Power_W: 0.063; Value2: 0.063W; VDC_V: 50; TempCo: 100 ppm/C; SizeArea_mm2: 0.5; SizeZ_mm: 0.6; EIA_Code: E96; U/M: EA; AEC Category: Q200
R20 R21 = CRCW0402365RFKED: RES, 365, 1%, 0.063 W, 0402; Manufacturer: Vishay-Dale; CompType: Resistor; Value: 365; Value_Code: 365R; Tolerance_%: 1; Power_W: 0.063; Value2: 0.063W; VDC_V: 50; TempCo: 100 ppm/C; SizeArea_mm2: 0.5; SizeZ_mm: 0.6; EIA_Code: E96; U/M: EA; AEC Category: Q200
R22 = CRCW040210K0FKED: RES, 10.0 k, 1%, 0.063 W, 0402; Manufacturer: Vishay-Dale; CompType: Resistor; Value: 10.0k; Res_ohm: 10000; Value_Code: 10k0; Tolerance_%: 1; Power_W: 0.063; Value2: 0.063W; VDC_V: 50; TempCo: 100 ppm/C; SizeArea_mm2: 0.5; SizeZ_mm: 0.6; EIA_Code: E96; U/M: EA; AEC Category: Q200
R551 R552 R592 R604 R646-R653 = CRCW02010000Z0ED: RES, 0, 5%, 0.05 W, 0201; Manufacturer: Vishay-Dale; CompType: Resistor; Value: 0; Value_Code: 0000; Tolerance_%: 5; Power_W: 0.05; Value2: 0.05W; TempCo: ppm/C; SizeArea_mm2: 0.18; SizeX_mm: 0.6; SizeY_mm: 0.3; SizeZ_mm: 0.26; EIA_Code: E24; U/M: EA; AEC Category: Q200; AEC Qualified: N
R555 = FC0402E50R0BTBST1: RES, 50, 0.1%, 0.5 W, 0402; Manufacturer: Vishay Thin Film; CompType: Resistor; Value: 50; Value_Code: 50R0; Tolerance_%: 0.1; Power_W: 0.5; Value2: 0.5W; TempCo: 0.1 ppm/C; SizeX_mm: 1; SizeZ_mm: 0.6; U/M: EA; AEC Category: Q200; AEC Qualified: N
U1 = LMH5401IRMSR: 8GHz Ultra Wideband Fully Differential Amplifier, RMS0014A (UQFN-14); Alternate PartNumber: LMH5401IRMST; Manufacturer: Texas Instruments; SymbolCreator: Altium; SizeArea_mm2: 6.25; SizeAreaWB_mm2: 12.25; SizeX_mm: 2.5; SizeZ_mm: 0.6; CompType: IC; U/M: EA
U2 = LMH6401IRMZR: 4.5 GHz Ultra Wideband Digital Variable Gain Amplifier, RMZ0016A (UQFN-HR-16); Alternate PartNumber: LMH6401IRMZT; Manufacturer: Texas Instruments; SymbolCreator: Altium; SizeArea_mm2: 9; SizeAreaWB_mm2: 16; SizeX_mm: 3; SizeZ_mm: 0.65; CompType: IC; U/M: EA
U3 = OPA376AIDCKT: Precision, Low Noise, Low Iq Operational Amplifier, 2.2 to 5.5 V, -40 to 125 degC, 5-pin SOT23 (DCK0005A), Green (RoHS & no Sb/Br); Manufacturer: Texas Instruments; Alternate PartNumber: Equivalent; CMRR(Min)(dB): 76; IIB(Max)(pA): 10; Iq per channel(Max)(mA): 0.95; Number of Channels: 1; Offset Drift(Typ)(uV/C): 0.32; Slew Rate(Typ)(V/us): 2; Sub Family: Low Input Bias Current Amp (<=10pA), Low Noise Amp (<=10nV/rtHz), Low Offset Voltage Amplifier (<=500uV), Low Supply Voltage Amplifier (<=2.7V), Precision Amplifier; Total Supply Voltage(Max)(+5V is 5, +/-5V is 10): 5.5; Total Supply Voltage(Min)(+5V is 5, +/-5V is 10): 2.2; Vio (25C)(Max)(mV): 0.025; Vn at 1kHz(Typ)(nV/rtHz): 7.5
U59 = BAL-0006SMG: Broadband Balun, 500 kHz to 6 GHz; Manufacturer: Marki Microwave; SymbolCreator: Altium; SizeAreaWB_mm2: 102.6169; SizeArea_mm2: 66.0969; SizeX_mm: 8.13; SizeZ_mm: 3.94
U65 U66 = CMP-0077784-1: Reflectionless Low Pass Filter, SMD; Manufacturer: Minicircuits; SizeArea_mm2: 9; SizeAreaWB_mm2: 16; SizeY_mm: 3; SizeZ_mm: 0.89

## Sheet TIDA-01022-E2_ADC ANALOG INP CH2.SchDoc: ADC12DJxx00_CH2
size 431 x 279 mm; Date: Not shown in title block; ApprovedBy: Not shown in title block; CheckedBy: Not shown in title block; Author: Not shown in title block; CompanyName: Not shown in title block; DrawnBy: Avinash N; Engineer: Not shown in title block; Organization: Not shown in title block; Address1: Not shown in title block; Address2: Not shown in title block; Address3: Not shown in title block; Address4: Not shown in title block; DocumentNumber: 1; Revision: Use project parameter SCH_Rev; SheetNumber: 3; SheetTotal: 26; PageSetup: Record=PageOptions¦CenterHorizontal=True¦CenterVertical=True¦PrintScale=1.00¦XCorrection=1.00¦YCorrection=1.00¦PrintKind=0¦BorderSize=5000000¦LeftOffset=0¦BottomOffset=0¦Orientation=2¦PaperLength=1000¦PaperWidth=1000¦Scale=100¦PaperSource=15¦PrintQuality=600¦MediaType=1¦DitherType=10¦PaperKind=Letter¦PrintScaleMode=1
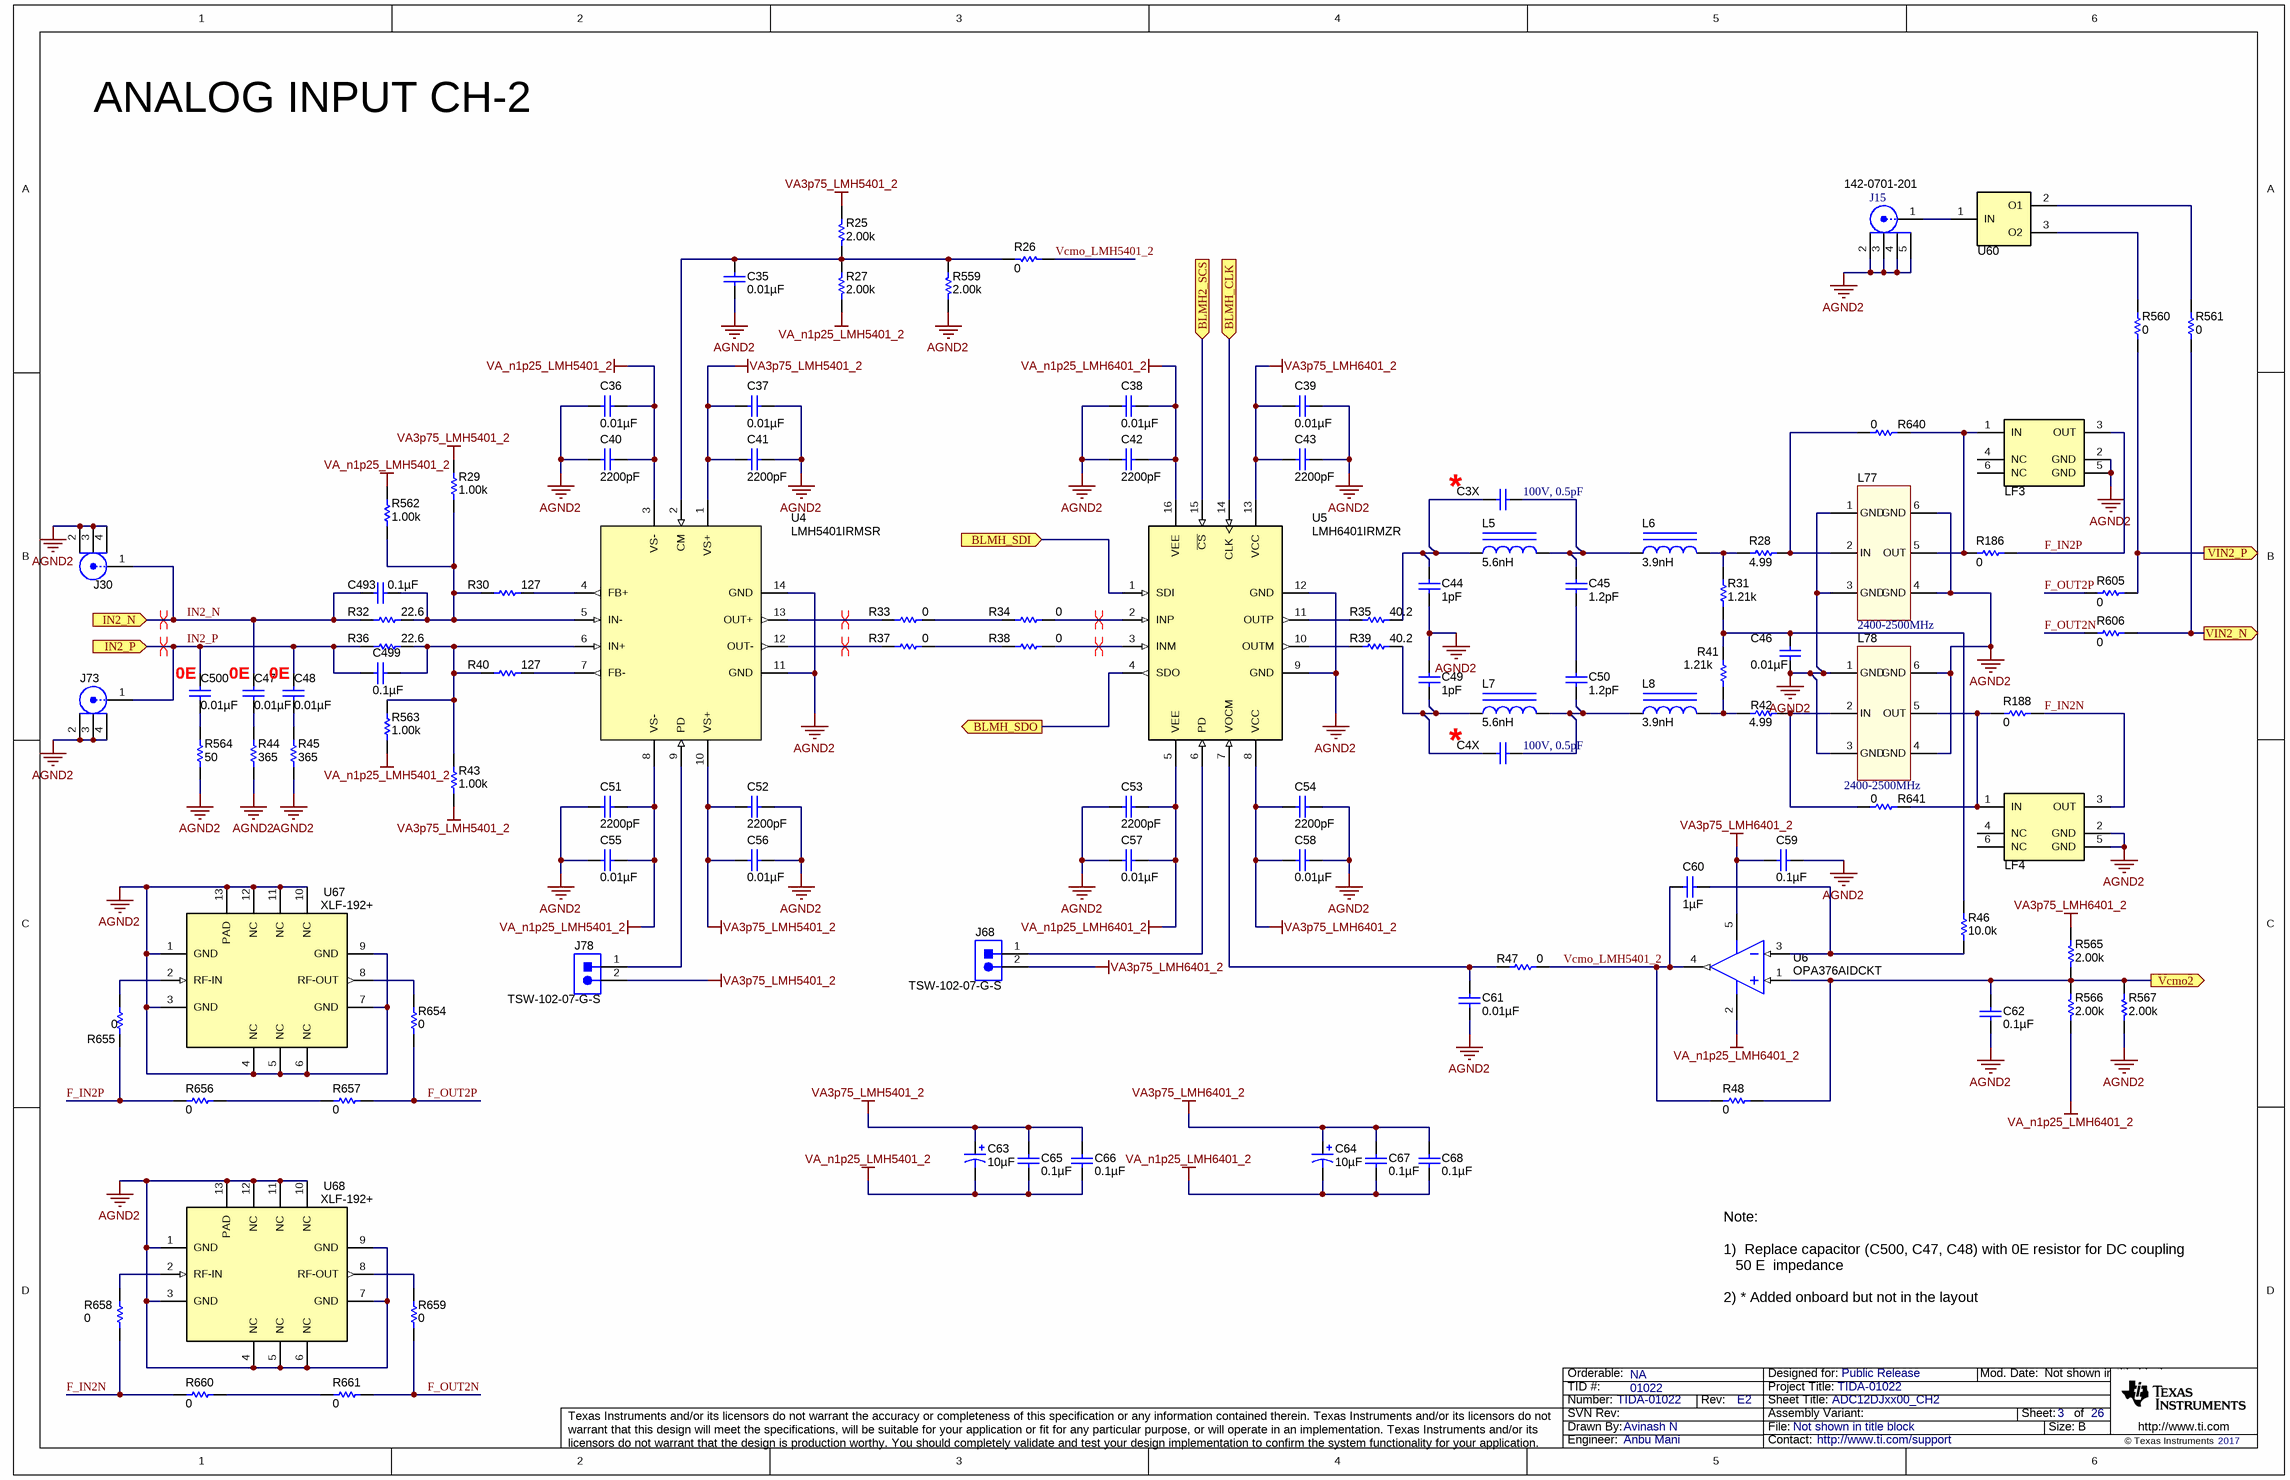
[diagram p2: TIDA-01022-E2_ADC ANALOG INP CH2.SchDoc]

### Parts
C3X  100V, 0.5pF  [0603_1.6x0.8x0.8mm_Reflow Soldering]
C4X  100V, 0.5pF  [0603_1.6x0.8x0.8mm_Reflow Soldering]
C35  ValueDisplayed: 0.01µF  [0402]  (hidden comment: GRM155R71E103KA01D)
C36  ValueDisplayed: 0.01µF  [0306]  (hidden comment: LLL185R71E103MA01L)
C37  ValueDisplayed: 0.01µF  [0306]  (hidden comment: LLL185R71E103MA01L)
C38  ValueDisplayed: 0.01µF  [0306]  (hidden comment: LLL185R71E103MA01L)
C39  ValueDisplayed: 0.01µF  [0306]  (hidden comment: LLL185R71E103MA01L)
C40  ValueDisplayed: 2200pF  [0306]  (hidden comment: LLL185R71H222MA01L)
C41  ValueDisplayed: 2200pF  [0306]  (hidden comment: LLL185R71H222MA01L)
C42  ValueDisplayed: 2200pF  [0306]  (hidden comment: LLL185R71H222MA01L)
C43  ValueDisplayed: 2200pF  [0306]  (hidden comment: LLL185R71H222MA01L)
C44  ValueDisplayed: 1pF  [0402]  (hidden comment: GRM1555C1H1R0CA01D)
C45  ValueDisplayed: 1.2pF  [0402]  (hidden comment: GRM1555C1H1R2BA01D)
C46  ValueDisplayed: 0.01µF  [0402]  (hidden comment: GRM155R71E103KA01D)
C47  ValueDisplayed: 0.01µF  [0402]  (hidden comment: GRM155R71E103KA01D)
C48  ValueDisplayed: 0.01µF  [0402]  (hidden comment: GRM155R71E103KA01D)
C49  ValueDisplayed: 1pF  [0402]  (hidden comment: GRM1555C1H1R0CA01D)
C50  ValueDisplayed: 1.2pF  [0402]  (hidden comment: GRM1555C1H1R2BA01D)
C51  ValueDisplayed: 2200pF  [0306]  (hidden comment: LLL185R71H222MA01L)
C52  ValueDisplayed: 2200pF  [0306]  (hidden comment: LLL185R71H222MA01L)
C53  ValueDisplayed: 2200pF  [0306]  (hidden comment: LLL185R71H222MA01L)
C54  ValueDisplayed: 2200pF  [0306]  (hidden comment: LLL185R71H222MA01L)
C55  ValueDisplayed: 0.01µF  [0306]  (hidden comment: LLL185R71E103MA01L)
C56  ValueDisplayed: 0.01µF  [0306]  (hidden comment: LLL185R71E103MA01L)
C57  ValueDisplayed: 0.01µF  [0306]  (hidden comment: LLL185R71E103MA01L)
C58  ValueDisplayed: 0.01µF  [0306]  (hidden comment: LLL185R71E103MA01L)
C59  ValueDisplayed: 0.1µF  [0402]  (hidden comment: C1005X5R1A104K050BA)
C60  ValueDisplayed: 1µF  [0603]  (hidden comment: C1608X5R1A105K080AC)
C61  ValueDisplayed: 0.01µF  [0402]  (hidden comment: GRM155R71E103KA01D)
C62  ValueDisplayed: 0.1µF  [0402]  (hidden comment: C1005X5R1A104K050BA)
C63  ValueDisplayed: 10µF  [3216-18]  (hidden comment: TPSA106K010R0900)
C64  ValueDisplayed: 10µF  [3216-18]  (hidden comment: TPSA106K010R0900)
C65  ValueDisplayed: 0.1µF  [0402]  (hidden comment: C1005X5R1A104K050BA)
C66  ValueDisplayed: 0.1µF  [0402]  (hidden comment: C1005X5R1A104K050BA)
C67  ValueDisplayed: 0.1µF  [0402]  (hidden comment: C1005X5R1A104K050BA)
C68  ValueDisplayed: 0.1µF  [0402]  (hidden comment: C1005X5R1A104K050BA)
C493  ValueDisplayed: 0.1µF  [0402]  (hidden comment: GRM155R71C104JA88D)
C499  ValueDisplayed: 0.1µF  [0402]  (hidden comment: GRM155R71C104JA88D)
C500  ValueDisplayed: 0.01µF  [0402]  (hidden comment: GRM155R71E103KA01D)
J15  142-0701-201  [Johnson_142-0701-20x]
J30  142-0771-831  [Johnson_142-0771-831]  (value not drawn)
J68  TSW-102-07-G-S  [TSW-102-07-G-S]
J73  142-0771-831  [Johnson_142-0771-831]  (value not drawn)
J78  TSW-102-07-G-S  [TSW-102-07-G-S]
L5  ValueDisplayed: 5.6nH  [LQW18A]  (hidden comment: LQW18AN5N6D10D)
L6  ValueDisplayed: 3.9nH  [0603HC]  (hidden comment: 0603HC-3N9XJLU)
L7  ValueDisplayed: 5.6nH  [LQW18A]  (hidden comment: LQW18AN5N6D10D)
L8  ValueDisplayed: 3.9nH  [0603HC]  (hidden comment: 0603HC-3N9XJLU)
L77  value 2400-2500MHz  [WE-LPF_0603]  (hidden comment: WE-LPF, 748112024)
L78  value 2400-2500MHz  [WE-LPF_0603]  (hidden comment: WE-LPF, 748112024)
LF3  LFL182G45TC3B746  [FIL_LFL18_TC1]  (value not drawn)
LF4  LFL182G45TC3B746  [FIL_LFL18_TC1]  (value not drawn)
R25  ValueDisplayed: 2.00k  [0402]  (hidden comment: CRCW04022K00FKED)
R26  ValueDisplayed: 0  [0402]  (hidden comment: CRCW04020000Z0ED)
R27  ValueDisplayed: 2.00k  [0402]  (hidden comment: CRCW04022K00FKED)
R28  ValueDisplayed: 4.99  [0402]  (hidden comment: CRCW04024R99FKED)
R29  ValueDisplayed: 1.00k  [0402]  (hidden comment: ERJ-2RKF1001X)
R30  ValueDisplayed: 127  [0402]  (hidden comment: CRCW0402127RFKED)
R31  ValueDisplayed: 1.21k  [0402]  (hidden comment: CRCW04021K21FKED)
R32  ValueDisplayed: 22.6  [0402]  (hidden comment: CRCW040222R6FKED)
R33  ValueDisplayed: 0  [0402]  (hidden comment: CRCW04020000Z0ED)
R34  ValueDisplayed: 0  [0402]  (hidden comment: CRCW04020000Z0ED)
R35  ValueDisplayed: 40.2  [0402]  (hidden comment: CRCW040240R2FKED)
R36  ValueDisplayed: 22.6  [0402]  (hidden comment: CRCW040222R6FKED)
R37  ValueDisplayed: 0  [0402]  (hidden comment: CRCW04020000Z0ED)
R38  ValueDisplayed: 0  [0402]  (hidden comment: CRCW04020000Z0ED)
R39  ValueDisplayed: 40.2  [0402]  (hidden comment: CRCW040240R2FKED)
R40  ValueDisplayed: 127  [0402]  (hidden comment: CRCW0402127RFKED)
R41  ValueDisplayed: 1.21k  [0402]  (hidden comment: CRCW04021K21FKED)
R42  ValueDisplayed: 4.99  [0402]  (hidden comment: CRCW04024R99FKED)
R43  ValueDisplayed: 1.00k  [0402]  (hidden comment: ERJ-2RKF1001X)
R44  ValueDisplayed: 365  [0402]  (hidden comment: CRCW0402365RFKED)
R45  ValueDisplayed: 365  [0402]  (hidden comment: CRCW0402365RFKED)
R46  ValueDisplayed: 10.0k  [0402]  (hidden comment: CRCW040210K0FKED)
R47  ValueDisplayed: 0  [0402]  (hidden comment: CRCW04020000Z0ED)
R48  ValueDisplayed: 0  [0402]  (hidden comment: CRCW04020000Z0ED)
R186  ValueDisplayed: 0  [0402_FILTER]  (hidden comment: CRCW04020000Z0ED)
R188  ValueDisplayed: 0  [0402_FILTER]  (hidden comment: CRCW04020000Z0ED)
R559  ValueDisplayed: 2.00k  [0402]  (hidden comment: CRCW04022K00FKED)
R560  ValueDisplayed: 0  [0201_adc]  (hidden comment: CRCW02010000Z0ED)
R561  ValueDisplayed: 0  [0201_adc]  (hidden comment: CRCW02010000Z0ED)
R562  ValueDisplayed: 1.00k  [0402]  (hidden comment: ERJ-2RKF1001X)
R563  ValueDisplayed: 1.00k  [0402]  (hidden comment: ERJ-2RKF1001X)
R564  ValueDisplayed: 50  [0402]  (hidden comment: FC0402E50R0BTBST1)
R565  ValueDisplayed: 2.00k  [0402]  (hidden comment: CRCW04022K00FKED)
R566  ValueDisplayed: 2.00k  [0402]  (hidden comment: CRCW04022K00FKED)
R567  ValueDisplayed: 2.00k  [0402]  (hidden comment: CRCW04022K00FKED)
R605  ValueDisplayed: 0  [0201_adc]  (hidden comment: CRCW02010000Z0ED)
R606  ValueDisplayed: 0  [0201_adc]  (hidden comment: CRCW02010000Z0ED)
R640  ValueDisplayed: 0  [0402_FILTER]  (hidden comment: CRCW04020000Z0ED)
R641  ValueDisplayed: 0  [0402_FILTER]  (hidden comment: CRCW04020000Z0ED)
R654  ValueDisplayed: 0  [0201_adc]  (hidden comment: CRCW02010000Z0ED)
R655  ValueDisplayed: 0  [0201_adc]  (hidden comment: CRCW02010000Z0ED)
R656  ValueDisplayed: 0  [0201_adc]  (hidden comment: CRCW02010000Z0ED)
R657  ValueDisplayed: 0  [0201_adc]  (hidden comment: CRCW02010000Z0ED)
R658  ValueDisplayed: 0  [0201_adc]  (hidden comment: CRCW02010000Z0ED)
R659  ValueDisplayed: 0  [0201_adc]  (hidden comment: CRCW02010000Z0ED)
R660  ValueDisplayed: 0  [0201_adc]  (hidden comment: CRCW02010000Z0ED)
R661  ValueDisplayed: 0  [0201_adc]  (hidden comment: CRCW02010000Z0ED)
U4  LMH5401IRMSR  [RMS0014A]
U5  LMH6401IRMZR  [RMZ0016A]
U6  OPA376AIDCKT  [DCK0005A_N]
U60  BAL-0006SMG  [Marki_BAL-0006SMG]  (value not drawn)
U67  XLF-192+  [DQ1225]
U68  XLF-192+  [DQ1225]

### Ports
BLMH2_SCS (in), BLMH_CLK (in), BLMH_SDI (in), BLMH_SDO (out), IN2_N (in), IN2_P (in), Vcmo2 (out), VIN2_N (out), VIN2_P (out)

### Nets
AGND2: C35.2 C36.1 C37.1 C38.1 C39.1 C40.2 C41.2 C42.2 C43.2 C44.2 C46.2 C49.2 C51.2 C52.2 C53.2 C54.2 C55.1 C56.1 C57.1 C58.1 C59.1 C61.2 C62.2 J15.2 J15.3 J15.4 J15.5 J30.2 J30.3 J30.4 J73.2 J73.3 J73.4 L77.1(GND) L77.3(GND) L77.4(GND) L77.6(GND) L78.1(GND) L78.3(GND) L78.4(GND) L78.6(GND) LF3.2(GND) LF3.5(GND) LF4.2(GND) LF4.5(GND) R44.1 R45.1 R559.1 R564.1 R567.1 U4.11(GND) U4.14(GND) U5.9(GND) U5.12(GND) U67.1(GND) U67.3(GND) U67.4(NC) U67.5(NC) U67.6(NC) U67.7(GND) U67.9(GND) U67.10(NC) U67.11(NC) U67.12(NC) U67.13(PAD) U68.1(GND) U68.3(GND) U68.4(NC) U68.5(NC) U68.6(NC) U68.7(GND) U68.9(GND) U68.10(NC) U68.11(NC) U68.12(NC) U68.13(PAD)  [project net AGND]
VA3p75_LMH5401_2: C37.2 C41.1 C52.1 C56.2 C63.1(+) C65.1 C66.1 J78.2 R25.2 R29.2 R43.1 U4.1(VS+) U4.10(VS+)
VA3p75_LMH6401_2: C39.2 C43.1 C54.1 C58.2 C59.2 C64.1(+) C67.1 C68.1 J68.2 R565.2 U5.8(VCC) U5.13(VCC) U6.5(V+)
VA_n1p25_LMH5401_2: C36.2 C40.1 C51.1 C55.2 C63.2(-) C65.2 C66.2 R27.1 R562.2 R563.2 U4.3(VS-) U4.8(VS-)
VA_n1p25_LMH6401_2: C38.2 C42.1 C53.1 C57.2 C64.2(-) C67.2 C68.2 R566.1 U5.5(VEE) U5.16(VEE) U6.2(V-)
BLMH2_SCS: U5.15(~{CS}) ; port BLMH2_SCS
BLMH_CLK: U5.14(CLK) ; port BLMH_CLK
BLMH_SDI: U5.1(SDI) ; port BLMH_SDI
BLMH_SDO: U5.4(SDO) ; port BLMH_SDO
F_IN2N: LF4.3(OUT) R188.2 R658.1 R660.1
F_IN2P: LF3.3(OUT) R186.2 R655.1 R656.1
F_OUT2N: R606.1 R659.1 R661.2
F_OUT2P: R605.1 R654.1 R657.2
IN2_N: C47.1 C493.2 J30.1 R32.1 ; port IN2_N
IN2_P: C48.1 C499.1 C500.1 J73.1 R36.1 ; port IN2_P
Vcmo2: C62.1 R48.1 R565.1 R566.2 R567.2 U6.1(IN+) ; port Vcmo2
Vcmo_LMH5401_2: C60.1 R26.2 R47.1 R48.2 U6.4(OUT)
VIN2_N: R561.2 R606.2 ; port VIN2_N
VIN2_P: R560.2 R605.2 ; port VIN2_P
NetC3X_1: C3X.1 C44.1 L5.1 R35.1
NetC3X_2: C3X.2 C45.1 L5.2 L6.1
NetC4X_1: C4X.1 C49.1 L7.1 R39.1
NetC4X_2: C4X.2 C50.1 L7.2 L8.1
NetC35_1: C35.1 R25.1 R26.1 R27.2 R559.2 U4.2(CM)
NetC45_2: C45.2 C50.2
NetC46_1: C46.1 R31.1 R41.1 R46.2
NetC47_2: C47.2 R44.2
NetC48_2: C48.2 R45.2
NetC60_2: C60.2 R46.1 U6.3(IN-)
NetC61_1: C61.1 R47.2 U5.7(VOCM)
NetC493_1: C493.1 R29.1 R30.1 R32.2 R562.1 U4.5(IN-)
NetC499_2: C499.2 R36.2 R40.1 R43.2 R563.1 U4.6(IN+)
NetC500_2: C500.2 R564.2
NetJ15_1: J15.1 U60.1(IN)
NetJ68_1: J68.1 U5.6(PD)
NetJ78_1: J78.1 U4.9(PD)
NetL6_2: L6.2 R28.1 R31.2
NetL8_2: L8.2 R41.2 R42.1
NetL77_2: L77.2(IN) R28.2 R640.1
NetL77_5: L77.5(OUT) LF3.1(IN) R186.1 R640.2
NetL78_2: L78.2(IN) R42.2 R641.1
NetL78_5: L78.5(OUT) LF4.1(IN) R188.1 R641.2
NetR30_2: R30.2 U4.4(FB+)
NetR33_1: R33.1 U4.13(OUT+)
NetR33_2: R33.2 R34.2
NetR34_1: R34.1 U5.2(INP)
NetR35_2: R35.2 U5.11(OUTP)
NetR37_1: R37.1 U4.12(OUT-)
NetR37_2: R37.2 R38.2
NetR38_1: R38.1 U5.3(INM)
NetR39_2: R39.2 U5.10(OUTM)
NetR40_2: R40.2 U4.7(FB-)
NetR560_1: R560.1 U60.3(O2)
NetR561_1: R561.1 U60.2(O1)
NetR654_2: R654.2 U67.8(RF-OUT)
NetR655_2: R655.2 U67.2(RF-IN)
NetR656_2: R656.2 R657.1
NetR658_2: R658.2 U68.2(RF-IN)
NetR659_2: R659.2 U68.8(RF-OUT)
NetR660_2: R660.2 R661.1

Not connected (* = marked no-connect by the designer): LF3 4(NC) 6(NC); LF4 4(NC) 6(NC)

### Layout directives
differential pair: IN2_N, IN2_P, NetR33_1, NetR34_1, NetR37_1, NetR38_1

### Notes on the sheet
- ANALOG INPUT CH-2
- *
- (near C500) 0E
- (near C47) 0E
- (near C48) 0E
- Note:
  1)  Replace capacitor (C500, C47, C48) with 0E resistor for DC coupling
  50 E  impedance
  2) * Added onboard but not in the layout

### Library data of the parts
C3X C4X = 885012006086: as C1X on sheet TIDA-01022-E2_ADC ANALOG INP CH1
C35 C46-C48 C61 C500 = GRM155R71E103KA01D: as C1 on sheet TIDA-01022-E2_ADC ANALOG INP CH1
C36-C39 C55-C58 = LLL185R71E103MA01L: as C2 on sheet TIDA-01022-E2_ADC ANALOG INP CH1
C40-C43 C51-C54 = LLL185R71H222MA01L: as C6 on sheet TIDA-01022-E2_ADC ANALOG INP CH1
C44 C49 = GRM1555C1H1R0CA01D: as C10 on sheet TIDA-01022-E2_ADC ANALOG INP CH1
C45 C50 = GRM1555C1H1R2BA01D: as C11 on sheet TIDA-01022-E2_ADC ANALOG INP CH1
C59 C62 C65-C68 = C1005X5R1A104K050BA: as C25 on sheet TIDA-01022-E2_ADC ANALOG INP CH1
C60 = C1608X5R1A105K080AC: as C26 on sheet TIDA-01022-E2_ADC ANALOG INP CH1
C63 C64 = TPSA106K010R0900: as C29 on sheet TIDA-01022-E2_ADC ANALOG INP CH1
C493 C499 = GRM155R71C104JA88D: as C490 on sheet TIDA-01022-E2_ADC ANALOG INP CH1
J15 = 142-0701-201: as J12 on sheet TIDA-01022-E2_ADC ANALOG INP CH1
J30 J73 = 142-0771-831: as J13 on sheet TIDA-01022-E2_ADC ANALOG INP CH1
J68 J78 = TSW-102-07-G-S: as J64 on sheet TIDA-01022-E2_ADC ANALOG INP CH1
L5 L7 = LQW18AN5N6D10D: as L1 on sheet TIDA-01022-E2_ADC ANALOG INP CH1
L6 L8 = 0603HC-3N9XJLU: as L2 on sheet TIDA-01022-E2_ADC ANALOG INP CH1
L77 L78 = WE-LPF, 748112024: as L75 on sheet TIDA-01022-E2_ADC ANALOG INP CH1
LF3 LF4 = LFL182G45TC3B746: as LF1 on sheet TIDA-01022-E2_ADC ANALOG INP CH1
R25 R27 R559 R565-R567 = CRCW04022K00FKED: as R1 on sheet TIDA-01022-E2_ADC ANALOG INP CH1
R26 R33 R34 R37 R38 R47 R48 R186 R188 R640 R641 = CRCW04020000Z0ED: as R2 on sheet TIDA-01022-E2_ADC ANALOG INP CH1
R28 R42 = CRCW04024R99FKED: as R4 on sheet TIDA-01022-E2_ADC ANALOG INP CH1
R29 R43 R562 R563 = ERJ-2RKF1001X: as R5 on sheet TIDA-01022-E2_ADC ANALOG INP CH1
R30 R40 = CRCW0402127RFKED: as R6 on sheet TIDA-01022-E2_ADC ANALOG INP CH1
R31 R41 = CRCW04021K21FKED: as R7 on sheet TIDA-01022-E2_ADC ANALOG INP CH1
R32 R36 = CRCW040222R6FKED: as R8 on sheet TIDA-01022-E2_ADC ANALOG INP CH1
R35 R39 = CRCW040240R2FKED: as R11 on sheet TIDA-01022-E2_ADC ANALOG INP CH1
R44 R45 = CRCW0402365RFKED: as R20 on sheet TIDA-01022-E2_ADC ANALOG INP CH1
R46 = CRCW040210K0FKED: as R22 on sheet TIDA-01022-E2_ADC ANALOG INP CH1
R560 R561 R605 R606 R654-R661 = CRCW02010000Z0ED: as R551 on sheet TIDA-01022-E2_ADC ANALOG INP CH1
R564 = FC0402E50R0BTBST1: as R555 on sheet TIDA-01022-E2_ADC ANALOG INP CH1
U4 = LMH5401IRMSR: as U1 on sheet TIDA-01022-E2_ADC ANALOG INP CH1
U5 = LMH6401IRMZR: as U2 on sheet TIDA-01022-E2_ADC ANALOG INP CH1
U6 = OPA376AIDCKT: as U3 on sheet TIDA-01022-E2_ADC ANALOG INP CH1
U60 = BAL-0006SMG: as U59 on sheet TIDA-01022-E2_ADC ANALOG INP CH1
U67 U68 = CMP-0077784-1: as U65 on sheet TIDA-01022-E2_ADC ANALOG INP CH1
